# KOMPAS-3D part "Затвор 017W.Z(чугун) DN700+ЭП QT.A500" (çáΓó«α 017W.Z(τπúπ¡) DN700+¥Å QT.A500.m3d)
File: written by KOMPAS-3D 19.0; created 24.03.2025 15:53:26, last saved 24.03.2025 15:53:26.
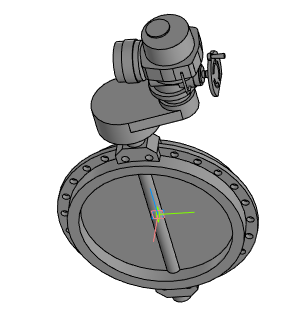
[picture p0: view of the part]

Document properties: Полное имя файла: Затвор 017W.Z(чугун) DN700+ЭП QT.A500.a3d

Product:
- Part/product: Затвор 017W.Z(чугун) DN700+ЭП QT.A500
    Масса: 554.418

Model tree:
1. Операция без истории:1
